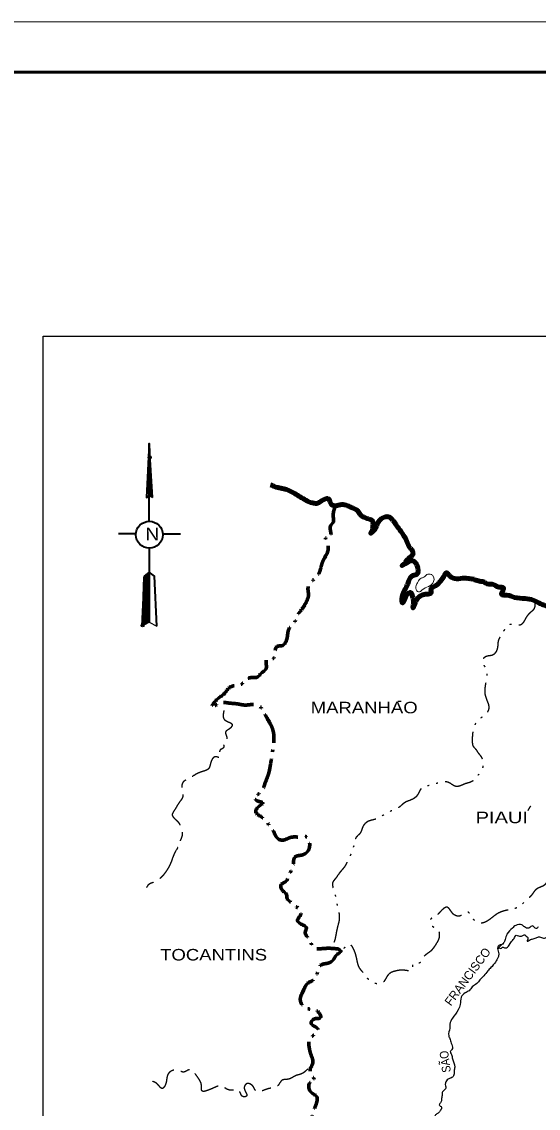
# Model space of a CAD drawing. Extents: x 512883 to 1063249, y 8784064 to 9081064.
# Drawn here: x 950481 to 1001709, y 8973228 to 9081064 of the extents above; entities that cross this region are included whole.
import ezdxf

# ---------------------------------------------------------------- set-up
doc = ezdxf.new("R2010")
doc.units = 0
doc.header["$LTSCALE"] = 600
doc.header["$PDMODE"] = 32
doc.header["$PDSIZE"] = 300
for name, pattern in [('DASH_DOUBLE_DOT', [9.2, 5, -1.2, 0.3, -1.2, 0.3, -1.2]), ('DOT_DASHED', [7.7, 5, -1.2, 0.3, -1.2]), ('LONG_DASH_SHORT_DASH', [9.9, 6, -1.2, 1.5, -1.2])]:
    doc.linetypes.add(name, pattern=pattern)
for name, color, linetype, lineweight in [('1', 7, 'Continuous', 25), ('10', 7, 'Continuous', 53), ('3', 7, 'Continuous', 25)]:
    doc.layers.add(name, color=color, linetype=linetype, lineweight=lineweight)

msp = doc.modelspace()

# ---------------------------------------------------------------- linework, layer by layer
at = {"layer": '1'}
for p, q in [((963115.9, 9039189), (963170.4, 9037281.1)), ((963170.4, 9038698.4), (963170.4, 9037281.1)), ((963224.9, 9037281.1), (963170.4, 9038698.4)), ((963170.4, 9037826.2), (963170.4, 9037281.1)), ((963224.9, 9037281.1), (963170.4, 9037826.2)), ((963115.9, 9034010.5), (963443, 9033847)), ((962407.3, 9021091.6), (963115.9, 9021473.2)), ((963115.9, 9021473.2), (963879.1, 9021091.6)), ((998111.5, 8989475.7), (997675.4, 8989039.6))]:
    msp.add_line(p, q, dxfattribs=at)
at = {"layer": '1', "lineweight": 35}
for p, q in [((963170.4, 9037281.1), (963170.4, 9034065)), ((963170.4, 9037281.1), (963224.9, 9034065)), ((963170.4, 9037281.1), (963224.9, 9034065)), ((963334, 9033956), (963224.9, 9037281.1)), ((963388.5, 9033901.5), (963224.9, 9037281.1)), ((963115.9, 9031503), (963115.9, 9034010.5)), ((961807.7, 9030249.3), (960063.3, 9030249.3)), ((964478.7, 9030249.3), (966223, 9030249.3)), ((962625.3, 9026052), (962407.3, 9021091.6)), ((962461.8, 9021146.1), (962625.3, 9025943)), ((963115.9, 9026433.6), (962625.3, 9026052))]:
    msp.add_line(p, q, dxfattribs=at)
at = {"layer": '1', "lineweight": 13}
for p, q in [((963170.4, 9034065), (963388.5, 9033901.5)), ((963224.9, 9034065), (963334, 9033956)), ((963224.9, 9034065), (963334, 9034010.5)), ((963115.9, 9026433.6), (962625.3, 9026052)), ((962625.3, 9025943), (962679.8, 9025997.5)), ((963006.9, 9021527.7), (962625.3, 9021309.6)), ((962952.4, 9021527.7), (962679.8, 9021364.1)), ((962897.9, 9021527.7), (962734.3, 9021418.7)), ((962843.4, 9021527.7), (962788.8, 9021527.7)), ((963115.9, 9021473.2), (962516.3, 9021200.6)), ((963061.4, 9021473.2), (962570.8, 9021255.1))]:
    msp.add_line(p, q, dxfattribs=at)
for points in [[(512883.1, 8784063.9), (1063248.6, 8784063.9), (1063248.6, 9081063.9), (512883.1, 9081063.9)], [(537883.1, 9076063.9), (1058248.6, 9076063.9), (1058248.6, 8789063.9), (537883.1, 8789063.9)]]:
    msp.add_lwpolyline(points, close=True, dxfattribs=at)
at = {"layer": '1', "lineweight": 53}
msp.add_lwpolyline([(537883.1, 8789063.9), (1058248.6, 8789063.9), (1058248.6, 9076063.9), (537883.1, 9076063.9)], close=True, dxfattribs=at)
at = {"layer": '1'}
msp.add_lwpolyline([(952595.4, 9049873), (1052567.1, 9049873), (1052567.1, 8921774), (952595.4, 8921774)], close=True, dxfattribs=at)
msp.add_lwpolyline([(952595.4, 9049873), (1052567.1, 9049873), (1052567.1, 8921774), (952595.4, 8921774)], close=True, dxfattribs=at)
at = {"layer": '1', "lineweight": 35}
for points in [[(963443, 9033847), (963115.9, 9039189), (962843.4, 9033847), (963115.9, 9034010.5), (963115.9, 9039189)], [(963334, 9034010.5), (963224.9, 9035863.8), (963279.4, 9034065)], [(963115.9, 9028832), (963115.9, 9026433.6), (963115.9, 9021473.2)], [(962516.3, 9021200.6), (962679.8, 9025943), (963115.9, 9026324.6), (963061.4, 9021473.2)], [(962570.8, 9021255.1), (962734.3, 9025943), (963061.4, 9026215.6), (963006.9, 9021527.7)], [(962625.3, 9021309.6), (962788.8, 9025943), (963006.9, 9026161), (962952.4, 9021527.7)], [(962679.8, 9025997.5), (963115.9, 9026379.1), (963115.9, 9021473.2)], [(962679.8, 9021364.1), (962843.4, 9025943), (962952.4, 9026052), (962897.9, 9021527.7)], [(962734.3, 9021418.7), (962843.4, 9025834), (962897.9, 9025943), (962843.4, 9021527.7)], [(962788.8, 9021527.7), (962843.4, 9025888.5), (963061.4, 9026270.1)], [(963879.1, 9021091.6), (963661, 9026052), (963115.9, 9026433.6)]]:
    msp.add_lwpolyline(points, dxfattribs=at)
at = {"layer": '1', "lineweight": 13}
for points in [[(963279.4, 9034065), (963334, 9034065), (963279.4, 9034228.6), (963170.4, 9034065)], [(962407.3, 9021091.6), (963115.9, 9021473.2), (962461.8, 9021146.1)]]:
    msp.add_lwpolyline(points, dxfattribs=at)
at = {"layer": '1', "lineweight": 35}
msp.add_circle((963141, 9030146.2), 1339.3, dxfattribs=at)
at = {"layer": '1', "lineweight": 140}
for points in [[(975162.7, 9035100.7), (975871.3, 9034828.2), (976470.9, 9034719.1), (977561.1, 9034228.6), (978106.2, 9033901.5), (978651.3, 9033574.4), (979305.4, 9033301.9), (979905.1, 9033301.9), (980395.6, 9033628.9), (980940.7, 9033683.4), (981158.8, 9033192.8), (981594.9, 9033029.3), (982194.5, 9033138.3), (982794.1, 9033029.3), (983284.7, 9032811.3), (983775.3, 9032538.7), (984047.8, 9032157.2), (984429.4, 9031884.6), (985029, 9031666.6), (985247, 9031557.6), (985301.6, 9031012.4), (985192.5, 9030467.3), (985083.5, 9030303.8), (985410.6, 9030576.4), (985683.1, 9031067), (985955.7, 9031557.6), (986446.3, 9031884.6), (986827.8, 9031939.1), (987263.9, 9031612.1), (987536.5, 9031230.5), (987863.5, 9030794.4), (988354.1, 9030085.8), (988681.2, 9029486.2), (988953.7, 9028886.6), (989226.3, 9028559.5), (989280.8, 9028232.4), (988899.2, 9027850.8), (988681.2, 9027632.8), (988354.1, 9027196.7), (988190.6, 9027087.7), (988681.2, 9027360.3), (989171.8, 9027578.3), (989444.3, 9027469.3), (989662.4, 9027142.2), (989771.4, 9026760.7), (989716.9, 9026270.1), (989280.8, 9026106.5), (988844.7, 9025506.9), (988681.2, 9025070.8), (988190.6, 9023762.6), (988245.1, 9023381), (988408.6, 9023599.1), (988790.2, 9024307.7), (989062.8, 9024416.7), (989226.3, 9024035.1), (989335.3, 9023653.6), (989335.3, 9023272), (989280.8, 9022890.4), (989498.8, 9023381), (989716.9, 9023817.1), (990153, 9024144.2), (990643.6, 9024253.2), (991079.6, 9024362.2), (991079.6, 9024798.3), (991515.7, 9025070.8), (991897.3, 9025397.9), (992333.4, 9025997.5), (992605.9, 9026379.1), (992987.5, 9025997.5), (993587.1, 9025779.5), (994404.8, 9025834), (995004.4, 9025779.5), (995385.9, 9025725)], [(995385.9, 9025670.5), (995658.5, 9025615.9), (996094.6, 9025506.9), (996258.1, 9025506.9), (996367.1, 9025452.4)], [(996367.1, 9025452.4), (996476.1, 9025343.4), (997184.8, 9025234.4), (997784.4, 9024961.8), (998275, 9024852.8), (998056.9, 9024253.2), (998602, 9024144.2), (999365.2, 9023926.1), (1000400.9, 9023817.1), (1001218.5, 9023653.6), (1001763.6, 9023381), (1002472.3, 9023108.5), (1003126.4, 9022999.5), (1003889.5, 9023163), (1004543.7, 9023217.5), (1005633.9, 9023381)]]:
    msp.add_spline(points, degree=3, dxfattribs=at)
at = {"layer": '1', "lineweight": 13}
msp.add_spline([(990643.6, 9026215.6), (991079.6, 9026215.6), (991297.7, 9026052), (991243.2, 9025343.4), (990807.1, 9025016.3), (990207.5, 9024689.3), (989825.9, 9024471.2), (989662.4, 9024580.2), (989607.9, 9025125.3), (989771.4, 9025452.4), (990098.5, 9025834), (990371, 9025943), (990643.6, 9026215.6)], degree=3, dxfattribs=at)
at = {"layer": '1', "linetype": 'DASH_DOUBLE_DOT'}
for points in [[(1001382.1, 9023490), (1001273, 9022781.4), (1000891.5, 9022399.8), (1000455.4, 9021854.7), (999964.8, 9021200.6), (999419.7, 9021200.6), (998820.1, 9021200.6), (998384, 9020764.5), (998002.4, 9020164.9), (997729.9, 9019565.3), (997675.4, 9019020.2), (997184.8, 9018202.6), (996639.7, 9018093.5), (996149.1, 9017657.5), (996367.1, 9017112.3), (996585.2, 9016458.2), (996421.6, 9014332.3), (996694.2, 9013514.7), (996803.2, 9012969.6), (996530.7, 9012370), (995767.5, 9011770.3), (995167.9, 9009535.4), (995222.4, 9009208.4), (995495, 9008881.3), (995713, 9008554.2), (996040.1, 9008118.2), (996203.6, 9007082.5), (995985.6, 9006537.4), (995549.5, 9006101.3), (995222.4, 9005719.7), (994513.8, 9005447.2), (993532.6, 9005174.6), (992824, 9005556.2), (991951.8, 9005556.2), (991025.1, 9005283.6), (990153, 9005011.1), (989716.9, 9004302.5), (989171.8, 9003866.4), (988517.7, 9003593.8), (987754.5, 9002994.2), (987100.4, 9002721.7), (986282.7, 9002285.6), (985519.6, 9001904), (984811, 9001686), (984320.4, 9001195.4), (984047.8, 9000541.2), (983557.2, 8999941.6), (983502.7, 8999396.5), (983393.7, 8999233), (983175.7, 8998578.9), (982848.6, 8997924.8), (982576.1, 8997325.2), (981976.4, 8996562), (981594.9, 8996016.9), (981322.3, 8995635.3), (981376.8, 8995035.7), (981540.3, 8994490.6), (981703.9, 8993727.5), (981812.9, 8993127.9), (981921.9, 8992691.8), (981976.4, 8992092.2), (981812.9, 8991274.5), (981649.4, 8990511.4), (981485.8, 8989802.7), (981104.3, 8989094.1)], [(1002908.3, 8996180.4), (1002690.3, 8995962.4), (1002417.8, 8995471.8), (1001545.6, 8994981.2), (1001000.5, 8994327.1), (1000346.4, 8993727.5), (999801.3, 8993236.9), (998711.1, 8992909.8), (997729.9, 8992582.8), (996748.7, 8991874.1), (995931, 8991601.6), (995385.9, 8991874.1), (995058.9, 8992364.7), (994731.8, 8992691.8), (994077.7, 8992364.7), (993314.6, 8992473.7), (992605.9, 8993182.4), (992224.3, 8992964.3), (991461.2, 8992255.7), (991025.1, 8991983.2), (991134.2, 8991383.5), (991788.3, 8990892.9), (991897.3, 8990456.9), (991788.3, 8989911.8), (991570.2, 8989530.2), (990970.6, 8988767.1), (990316.5, 8988221.9), (989880.4, 8987622.3), (989280.8, 8987567.8), (989226.3, 8986968.2), (988517.7, 8986913.7), (987591, 8986859.2), (986882.3, 8986532.1), (986228.2, 8985660), (985410.6, 8985660), (984756.5, 8986150.6), (984429.4, 8986586.6), (983938.8, 8987240.8), (983720.8, 8988003.9), (983393.7, 8989039.6), (983012.1, 8989475.7), (982576.1, 8989257.6), (982194.5, 8988821.6)]]:
    msp.add_spline(points, degree=3, dxfattribs=at)
at = {"layer": '1', "linetype": 'LONG_DASH_SHORT_DASH'}
for points in [[(970529.3, 9012697), (970529.3, 9011879.4), (971019.9, 9011552.3), (971347, 9011334.3), (971019.9, 9010843.7), (970692.8, 9010571.1), (970801.8, 9009862.5), (970529.3, 9009589.9), (970474.8, 9008990.3), (970147.7, 9008772.3), (970147.7, 9008009.1), (969766.2, 9008118.2), (969221.1, 9007518.6), (969003, 9006918.9), (968403.4, 9006646.4), (967858.3, 9006428.3), (967313.2, 9006101.3), (966931.6, 9005883.2), (966495.5, 9005610.7), (966386.5, 9004793), (966441, 9004138.9), (966114, 9003593.8), (965568.9, 9002721.7), (965405.3, 9002394.6), (965950.4, 9001686), (966277.5, 9001031.8), (966386.5, 9000323.2), (966168.5, 8999723.6), (966005, 8999233), (965623.4, 8998524.4), (965350.8, 8997815.7), (965023.8, 8997107.1), (964587.7, 8996453), (964097.1, 8995962.4), (963497.5, 8995635.3), (963061.4, 8995417.3), (962734.3, 8994817.7)], [(978869.3, 8977156.4), (978269.7, 8976665.8), (977615.6, 8976447.7), (976961.5, 8976120.7), (976307.4, 8976011.7), (975871.3, 8975466.6), (975053.6, 8975194), (974399.5, 8974976), (973799.9, 8974867), (973418.3, 8975412.1), (973145.8, 8975630.1), (972873.2, 8975684.6), (972546.2, 8975248.5), (972764.2, 8974430.9), (972437.2, 8974376.4), (972001.1, 8975030.5), (971347, 8975030.5), (970801.8, 8975139.5), (970256.7, 8975466.6), (969766.2, 8975357.5), (969384.6, 8975194), (968839.5, 8974976), (968403.4, 8974921.5), (968294.4, 8975575.6), (968130.8, 8976011.7), (967749.3, 8976556.8), (967422.2, 8976938.3), (967095.2, 8977047.4), (966604.6, 8976829.3), (965950.4, 8976992.8), (965350.8, 8976938.3), (965023.8, 8976665.8), (964751.2, 8975630.1), (964424.2, 8975194), (963933.6, 8975630.1), (963443, 8975902.6)]]:
    msp.add_spline(points, degree=3, dxfattribs=at)
at = {"layer": '1'}
for points in [[(997675.4, 8989039.6), (997838.9, 8989148.6), (997947.9, 8989094.1), (998166, 8989203.1), (998438.5, 8989148.6), (998656.6, 8989203.1), (998983.6, 8989693.7), (999310.7, 8990075.3), (999528.7, 8990402.3), (999746.8, 8990347.8), (999964.8, 8990293.3), (1000237.3, 8990402.3), (1000400.9, 8990456.9), (1000509.9, 8990293.3), (1000673.4, 8990184.3), (1000618.9, 8989802.7), (1000946, 8989966.3), (1001109.5, 8990020.8), (1001491.1, 8990129.8), (1001818.1, 8990238.8), (1002036.2, 8990184.3), (1002417.8, 8990129.8), (1002744.8, 8990347.8), (1003071.9, 8990347.8), (1003398.9, 8990456.9), (1003617, 8990729.4), (1003726, 8991056.5), (1003780.5, 8991220), (1003944, 8991601.6), (1004107.6, 8991492.6), (1004271.1, 8991383.5), (1004598.2, 8991383.5), (1004816.2, 8991547.1), (1005088.8, 8991547.1), (1005361.3, 8991601.6)], [(1001709.1, 8991220), (1001491.1, 8991056.5), (1001164, 8991329), (1000782.5, 8991111), (1000346.4, 8991220), (1000073.8, 8991438.1), (999474.2, 8991383.5), (999147.1, 8991111), (998602, 8990511.4), (998438.5, 8989966.3), (998275, 8989639.2), (998220.5, 8989584.7)], [(1001709.1, 8991220), (1001491.1, 8991056.5), (1001164, 8991329), (1000782.5, 8991111), (1000346.4, 8991220), (1000073.8, 8991438.1), (999474.2, 8991383.5), (999147.1, 8991111), (998602, 8990511.4), (998438.5, 8989966.3), (998275, 8989639.2), (998220.5, 8989584.7)], [(998111.5, 8989475.7), (997784.4, 8989366.7), (997675.4, 8989094.1), (997784.4, 8988549), (997729.9, 8988221.9), (997457.3, 8987731.3), (997021.2, 8987186.2), (996694.2, 8986859.2), (996312.6, 8986368.6), (995931, 8985987), (995604, 8985605.5), (995167.9, 8985278.4), (994840.8, 8984896.8), (994459.3, 8984678.8), (994077.7, 8984242.7), (993968.7, 8983534.1), (993750.6, 8982989), (993205.5, 8982171.3), (992933, 8981571.7), (992933, 8981190.1), (992824, 8980427), (992987.5, 8980045.4), (993042, 8979827.4), (993205.5, 8979282.3), (993151, 8979064.2), (992987.5, 8978846.2), (993096.5, 8978573.6), (993205.5, 8978137.6), (993423.6, 8977319.9), (993369.1, 8976883.8), (993314.6, 8976447.7), (993042, 8976229.7), (992769.5, 8976120.7), (992496.9, 8975739.1), (992496.9, 8975466.6), (992551.4, 8975248.5), (992224.3, 8974867), (992169.8, 8974485.4), (992115.3, 8974103.8), (992060.8, 8973831.2), (991897.3, 8973558.7), (992115.3, 8973340.7), (992006.3, 8973013.6), (991788.3, 8972741.1), (991515.7, 8972577.5), (991461.2, 8971923.4), (991188.7, 8971378.3), (991025.1, 8970996.7), (990861.6, 8970560.6), (990698.1, 8970179.1), (990643.6, 8969743), (990425.5, 8969197.9), (990153, 8968816.3), (990043.9, 8968489.3), (989880.4, 8967998.7), (989771.4, 8967617.1), (989662.4, 8967290), (989498.8, 8966744.9), (989389.8, 8966145.3), (989171.8, 8965763.8), (988844.7, 8965436.7), (988572.2, 8965055.1), (988190.6, 8964564.5), (988136.1, 8964237.5), (987536.5, 8963692.4), (987263.9, 8963365.3), (986827.8, 8962874.7), (986500.8, 8962602.2), (986173.7, 8962329.6), (985901.2, 8962166.1), (985301.6, 8962166.1), (984974.5, 8961730), (984865.5, 8961348.4), (984483.9, 8961293.9), (984156.8, 8960912.3), (984156.8, 8959767.6)], [(998220.5, 8989584.7), (998220.5, 8989530.2), (998166, 8989530.2), (998111.5, 8989475.7)]]:
    msp.add_spline(points, degree=3, dxfattribs=at)
for p in [(963170.4, 9037826.2), (963224.9, 9034065), (962461.8, 9021146.1)]:
    msp.add_point(p, dxfattribs=at)
at = {"layer": '10', "lineweight": 25}
msp.add_lwpolyline([(537883.1, 9076063.9), (1058248.6, 9076063.9), (1058248.6, 8789063.9), (537883.1, 8789063.9)], close=True, dxfattribs=at)
at = {"layer": '3'}
msp.add_lwpolyline([(537883.1, 9076063.9), (1058248.6, 9076063.9), (1058248.6, 8789063.9), (537883.1, 8789063.9)], close=True, dxfattribs=at)
at = {"layer": '3', "linetype": 'DOT_DASHED', "lineweight": 70}
for points in [[(981594.9, 9033029.3), (981376.8, 9031939.1), (981376.8, 9031394), (981158.8, 9031121.5), (981104.3, 9030521.8), (981049.8, 9029867.7), (980613.7, 9029813.2), (980722.7, 9029431.7), (980886.2, 9028886.6), (980777.2, 9028341.4), (980450.2, 9027741.8), (980232.1, 9027196.7), (980014.1, 9026433.6), (979687, 9025888.5), (979087.4, 9025397.9), (978869.3, 9024743.8), (978923.9, 9024144.2), (978760.3, 9023599.1), (978324.2, 9022835.9), (977888.2, 9022236.3), (977506.6, 9021418.7), (977016, 9020873.6), (976798, 9019892.4), (976252.9, 9019129.2), (975816.8, 9019074.7), (975598.7, 9018366.1), (975435.2, 9017875.5), (974781.1, 9017766.5), (974726.6, 9016894.3), (974236, 9016403.7), (973854.4, 9016022.1), (973200.3, 9015967.6), (972764.2, 9015804.1), (972273.6, 9015313.5), (971456, 9015150), (970965.4, 9014877.4), (970583.8, 9014386.8), (969820.7, 9013787.2), (969275.6, 9012969.6), (970147.7, 9013460.2), (970910.9, 9013460.2), (971946.6, 9013351.1), (972655.2, 9013242.1), (973309.3, 9013296.6), (974181.5, 9013024.1), (974726.6, 9012097.4), (975217.2, 9011225.2), (975489.7, 9010189.6), (975435.2, 9009208.4), (975162.7, 9007409.5), (974944.6, 9006373.8), (974563.1, 9005338.1), (974127, 9004520.5), (973527.3, 9004084.4), (973799.9, 9003757.3), (974399.5, 9003539.3), (973963.4, 9003157.7), (973690.9, 9002612.6), (974290.5, 9002122), (974999.1, 9001358.9), (975435.2, 9000759.3), (975871.3, 8999996.2), (976307.4, 8999832.6), (977125, 9000105.2), (978160.7, 9000159.7), (978760.3, 9000159.7), (979032.9, 8999560.1), (978814.8, 8998687.9), (978269.7, 8998360.8), (977615.6, 8998197.3), (977343.1, 8997052.6), (976907, 8996289.5), (976743.5, 8995798.9), (976198.3, 8995417.3), (976361.9, 8994817.7), (976743.5, 8994436.1), (976798, 8994054.5), (977343.1, 8993563.9), (977670.1, 8993236.9), (978160.7, 8992909.8), (978106.2, 8992364.7), (977833.7, 8991874.1), (978324.2, 8991438.1), (978705.8, 8991165.5), (978596.8, 8990674.9), (978760.3, 8990293.3), (979141.9, 8989857.2), (979250.9, 8989312.2), (980559.2, 8989094.1), (981267.8, 8989094.1), (981867.4, 8989039.6)], [(981867.4, 8989039.6), (982140, 8988821.6), (981758.4, 8988494.5), (981376.8, 8987949.4), (980831.7, 8987622.3), (980177.6, 8987458.8), (979850.5, 8986859.2), (979469, 8985987), (978869.3, 8985660), (978433.3, 8984951.3), (978106.2, 8984024.7), (978433.3, 8983316), (979196.4, 8983043.5), (979959.6, 8982716.4), (980123.1, 8982225.8), (979414.5, 8982062.3), (979196.4, 8981626.2), (979850.5, 8981081.1), (979741.5, 8980754.1), (979032.9, 8980154.4), (978978.4, 8979336.8), (979196.4, 8978464.6), (979359.9, 8977756), (979087.4, 8977101.9), (979359.9, 8976338.7), (979523.5, 8975902.6), (979196.4, 8975848.1), (979087.4, 8974921.5), (979741.5, 8974376.4), (979632.5, 8973504.2), (979305.4, 8972577.5), (979196.4, 8971759.9), (979359.9, 8971051.2), (979741.5, 8970288.1), (980286.6, 8969688.5), (980341.1, 8968707.3), (980068.6, 8967726.1), (979905.1, 8966690.4), (979850.5, 8966036.3), (979469, 8965164.1), (987645.5, 8970724.2), (988572.2, 8969415.9), (989389.8, 8969034.4), (989498.8, 8968380.2), (989716.9, 8967726.1), (990425.5, 8967344.5), (991079.6, 8966854), (991515.7, 8966690.4), (992224.3, 8967181), (992714.9, 8967617.1), (993205.5, 8967235.5), (993805.1, 8966963), (994568.3, 8966417.9), (995167.9, 8965872.8), (995658.5, 8965382.2), (996367.1, 8965109.6), (996803.2, 8965109.6), (997511.8, 8964673.5), (998166, 8965000.6), (999038.1, 8965000.6), (999746.8, 8964237.5), (1000291.9, 8963528.8), (1000673.4, 8962874.7), (1000782.5, 8962220.6), (1000837, 8961621), (1001218.5, 8961675.5), (1001872.7, 8961675.5), (1002744.8, 8961730), (1003562.5, 8961566.5), (1004162.1, 8961348.4), (1004816.2, 8961184.9), (1005524.8, 8961021.4), (1006069.9, 8960639.8), (1006560.5, 8960149.2), (1007051.1, 8959658.6), (1007214.7, 8959113.5), (1006996.6, 8958077.8), (1006506, 8957369.2), (1006124.5, 8956769.6), (1005361.3, 8956551.5), (1004816.2, 8955842.9), (1004271.1, 8954807.2), (1003944, 8953717), (1003944, 8953171.9), (1004434.6, 8952354.2), (1004925.2, 8951918.2), (1005252.3, 8951046), (1005906.4, 8950609.9), (1006506, 8949955.8), (1007214.7, 8949737.8), (1008195.8, 8949901.3)]]:
    msp.add_spline(points, degree=3, dxfattribs=at)

# ---------------------------------------------------------------- texts
at = {"layer": '1'}
for s, height, width, p in [('N ', 1256, 1.15, (962734.3, 9029595.2)), ('MARANHAO', 1144, 1.2, (979141.9, 9012424.5)), ('PIAUI', 1144, 1.3, (995495, 9001522.4)), ('TOCANTINS', 1144, 1.2, (964206.1, 8987894.9))]:
    msp.add_text(s, height=height, dxfattribs=dict(at, width=width)).set_placement(p)
msp.add_text('-', height=1144, dxfattribs=at).set_placement((987700, 9013187.6))
for s, height, rotation, width, p in [('-', 1144, 59.434, 1.5, (1001000.5, 9002449.1)), ('SÃO', 858.2, 97.54, 0.9, (993042, 8976829.3))]:
    msp.add_text(s, height=height, rotation=rotation, dxfattribs=dict(at, width=width)).set_placement(p)
msp.add_text('FRANCISCO', height=858.5, rotation=53.575, dxfattribs=at).set_placement((993042, 8983316))

doc.saveas('drawing.dxf')
